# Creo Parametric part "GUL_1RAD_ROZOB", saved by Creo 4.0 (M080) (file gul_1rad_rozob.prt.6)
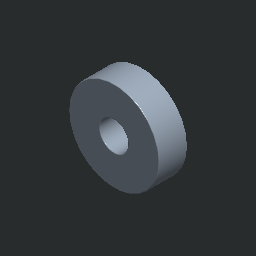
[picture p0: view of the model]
Units: millimeter Kilogram Sec (mmKs); MM, KILOGRAM, SECS
Materials in the file: OCEL_N

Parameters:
  MFG_WP_MATERIAL = "RO5_3"
  NAZOV = "GUL_1RAD_ROZOB"
  PTC_MATERIAL_NAME = "OCEL_N"

Other parameters: HMOTNOST, HUSTOTA

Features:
  1. round
  2. round

Named dimensions: velke_D

Layers: 1, 2, 3, 4, 5, 6, 7, 8, 9, 10, 11, 12, 13, 14, 15, 16, 17, 18, 19, 20, 21, 22, 23, 24, 25, 26, 27, 28, 29, 30, 31, 32

Family table entries: GENERIC, LOZISKO_E5, GUL_1RAD_ROZOB, value(d_val), 2/0, value(i_val), LOZISKO_E6, GUL_1RAD_ROZOB, 2/5, LOZISKO_E7, GUL_1RAD_ROZOB, 2/6, LOZISKO_E8, GUL_1RAD_ROZOB, !/ , 2/8, LOZISKO_E10, GUL_1RAD_ROZOB, !/$, 2/<, 2/ , LOZISKO_E12, GUL_1RAD_ROZOB, !/(, 2/@, LOZISKO_E15, GUL_1RAD_ROZOB, !/., 2/ , LOZISKO_E17, GUL_1RAD_ROZOB, !/1, 2/F, 2/&, LOZISKO_E20, GUL_1RAD_ROZOB, !/4, 2/(, # Pro/TABLE, [] S 92;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

Surfaces: 8 torus, 2 plane, 2 cylinder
